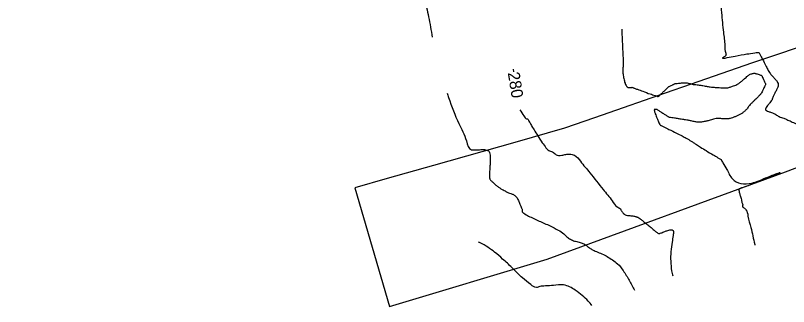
# Model space of a CAD drawing. Extents: x -478232 to -472707, y -1118753 to -1113967.
# Drawn here: x -476364.6 to -476102.7, y -1115350.3 to -1115251.7 of the extents above; entities that cross this region are included whole.
import ezdxf

# ---------------------------------------------------------------- set-up
doc = ezdxf.new("R2010")
doc.units = 0
for name, color, linetype in [('ObPÚ', 7, 'Continuous'), ('Vrstevnice_hlavni', 7, 'Continuous'), ('Vrstevnice_popis', 7, 'Continuous'), ('Vrstevnice_vedlejsi', 7, 'Continuous')]:
    doc.layers.add(name, color=color, linetype=linetype)

msp = doc.modelspace()

# ---------------------------------------------------------------- linework, layer by layer
at = {"layer": 'ObPÚ'}
msp.add_lwpolyline([(-476068.7, -1115252.31), (-476114.88, -1115267.73), (-476138.618, -1115276.003), (-476141.91, -1115277.15), (-476168.45, -1115286.39), (-476178.6, -1115289.93), (-476195.38, -1115294.7), (-476223.04, -1115302.55), (-476238.65, -1115306.98), (-476249.64, -1115310.1), (-476237.84, -1115350.34), (-476184.5, -1115334.29), (-476103.79, -1115304.74), (-476065.34, -1115290.09)], dxfattribs=at)
at = {"layer": 'Vrstevnice_hlavni'}
msp.add_line((-476196.015, -1115269.846), (-476195.861, -1115270.85), dxfattribs=at)
msp.add_spline([(-476193.757, -1115283.639), (-476192.399, -1115285.697), (-476191.876, -1115286.389), (-476191.509, -1115286.744), (-476191.298, -1115286.761), (-476191.153, -1115286.774), (-476191.075, -1115286.783), (-476191.063, -1115286.789), (-476190.853, -1115287.151), (-476190.446, -1115287.871), (-476189.842, -1115288.948), (-476188.923, -1115290.467), (-476187.688, -1115292.429), (-476186.137, -1115294.833), (-476184.891, -1115296.504), (-476183.948, -1115297.443), (-476183.309, -1115297.648), (-476182.68, -1115297.954), (-476182.06, -1115298.362), (-476181.45, -1115298.872), (-476180.595, -1115299.114), (-476179.497, -1115299.088), (-476178.155, -1115298.795), (-476176.997, -1115298.69), (-476176.025, -1115298.773), (-476175.238, -1115299.045), (-476173.224, -1115301.122), (-476169.984, -1115305.003), (-476165.518, -1115310.689), (-476162.449, -1115314.535), (-476160.779, -1115316.54), (-476160.507, -1115316.704), (-476160.264, -1115316.845), (-476160.048, -1115316.962), (-476159.86, -1115317.056), (-476159.707, -1115317.19), (-476159.59, -1115317.365), (-476159.508, -1115317.58), (-476159.311, -1115317.896), (-476158.998, -1115318.315), (-476158.57, -1115318.834), (-476158.007, -1115319.207), (-476157.308, -1115319.433), (-476156.473, -1115319.513), (-476155.76, -1115319.601), (-476155.169, -1115319.698), (-476154.699, -1115319.804), (-476154.303, -1115319.906), (-476153.978, -1115320.004), (-476153.727, -1115320.098), (-476153.145, -1115320.495), (-476152.232, -1115321.193), (-476150.988, -1115322.193), (-476149.831, -1115323.145), (-476148.761, -1115324.046), (-476147.778, -1115324.899), (-476147.017, -1115325.426), (-476146.478, -1115325.629), (-476146.16, -1115325.507), (-476145.635, -1115325.303), (-476144.904, -1115325.017), (-476143.967, -1115324.649), (-476143.233, -1115324.414), (-476142.702, -1115324.312), (-476142.375, -1115324.342), (-476142.123, -1115324.398), (-476141.945, -1115324.481), (-476141.842, -1115324.59), (-476141.767, -1115324.715), (-476141.722, -1115324.858), (-476141.705, -1115325.018), (-476141.842, -1115326.221), (-476142.131, -1115328.466), (-476142.574, -1115331.753), (-476142.636, -1115334.999), (-476142.32, -1115338.203), (-476141.962, -1115339.984)], degree=3, dxfattribs=at)
at = {"layer": 'Vrstevnice_vedlejsi'}
for points in [[(-476527.08, -1115263.803), (-476526.887, -1115263.69), (-476526.162, -1115262.721), (-476524.907, -1115260.894), (-476523.121, -1115258.209), (-476521.764, -1115256.313), (-476520.836, -1115255.206), (-476520.337, -1115254.886), (-476519.366, -1115254.043), (-476517.924, -1115252.676), (-476516.009, -1115250.786), (-476514.302, -1115249.024), (-476512.803, -1115247.392), (-476511.511, -1115245.89), (-476509.929, -1115244.508), (-476508.058, -1115243.246), (-476505.898, -1115242.105), (-476504.014, -1115241.274), (-476502.406, -1115240.753), (-476501.074, -1115240.543), (-476500.026, -1115240.386), (-476499.263, -1115240.283), (-476498.784, -1115240.233), (-476497.172, -1115239.574), (-476494.427, -1115238.305), (-476490.549, -1115236.427), (-476487.653, -1115234.652), (-476485.739, -1115232.982), (-476484.807, -1115231.416), (-476483.874, -1115229.496), (-476482.938, -1115227.221), (-476482, -1115224.593), (-476480.343, -1115222.339), (-476477.964, -1115220.46), (-476474.866, -1115218.956), (-476472.042, -1115216.696), (-476469.492, -1115213.68), (-476467.217, -1115209.908), (-476464.704, -1115205.831), (-476461.955, -1115201.448), (-476458.968, -1115196.76), (-476456.464, -1115193.232), (-476454.442, -1115190.863), (-476452.903, -1115189.654), (-476451.796, -1115188.78), (-476451.122, -1115188.24), (-476450.88, -1115188.036), (-476449.741, -1115187.407), (-476447.705, -1115186.353), (-476444.771, -1115184.875), (-476442.444, -1115183.754), (-476440.723, -1115182.99), (-476439.608, -1115182.582), (-476438.521, -1115182.379), (-476437.462, -1115182.381), (-476436.431, -1115182.589), (-476434.671, -1115182.945), (-476432.182, -1115183.449), (-476428.964, -1115184.102), (-476425.887, -1115183.927), (-476422.953, -1115182.925), (-476420.161, -1115181.095), (-476418.073, -1115179.463), (-476416.69, -1115178.026), (-476416.012, -1115176.786), (-476414.938, -1115175.626), (-476413.47, -1115174.546), (-476411.607, -1115173.546), (-476409.534, -1115172.603), (-476407.252, -1115171.715), (-476404.761, -1115170.883), (-476401.574, -1115169.794), (-476397.69, -1115168.447), (-476393.11, -1115166.843), (-476388.096, -1115165.135), (-476382.647, -1115163.324), (-476376.764, -1115161.408), (-476372.621, -1115160.054), (-476370.219, -1115159.261), (-476369.557, -1115159.028), (-476369.039, -1115158.854), (-476368.663, -1115158.738), (-476368.431, -1115158.68), (-476367.559, -1115158.618), (-476366.047, -1115158.551), (-476363.896, -1115158.479), (-476362.463, -1115158.431), (-476361.747, -1115158.407), (-476361.748, -1115158.407), (-476361.852, -1115158.365), (-476362.059, -1115158.28), (-476362.368, -1115158.152), (-476365.304, -1115157.405), (-476370.868, -1115156.037), (-476379.058, -1115154.05), (-476384.846, -1115152.681), (-476388.232, -1115151.932)], [(-476075.436, -1115157.873), (-476077.562, -1115158.907), (-476079.639, -1115159.964), (-476081.666, -1115161.045), (-476083.644, -1115162.149), (-476085.921, -1115163.289), (-476088.498, -1115164.465), (-476091.373, -1115165.676), (-476093.656, -1115166.843), (-476095.346, -1115167.967), (-476096.444, -1115169.047), (-476097.921, -1115170.165), (-476099.777, -1115171.319), (-476102.012, -1115172.511), (-476105.743, -1115173.677), (-476110.97, -1115174.816), (-476117.692, -1115175.928), (-476122.561, -1115177.005), (-476125.576, -1115178.045), (-476126.738, -1115179.05), (-476129.738, -1115180.989), (-476134.578, -1115183.864), (-476141.257, -1115187.673), (-476147.035, -1115190.356), (-476151.912, -1115191.911), (-476155.888, -1115192.338), (-476158.789, -1115192.754), (-476160.614, -1115193.159), (-476161.364, -1115193.552), (-476162.517, -1115193.939), (-476164.073, -1115194.319), (-476166.032, -1115194.693), (-476167.609, -1115195.158), (-476168.804, -1115195.715), (-476169.616, -1115196.364), (-476170.816, -1115197.116), (-476172.405, -1115197.973), (-476174.383, -1115198.934), (-476179.537, -1115202.555), (-476187.868, -1115208.836), (-476199.377, -1115217.776), (-476207.75, -1115223.932), (-476212.989, -1115227.302), (-476215.093, -1115227.888), (-476217.31, -1115229.046), (-476219.639, -1115230.776), (-476222.081, -1115233.079), (-476224.102, -1115235.091), (-476225.704, -1115236.812), (-476226.884, -1115238.243), (-476227.475, -1115239.561), (-476227.475, -1115240.767), (-476226.885, -1115241.861), (-476225.939, -1115245.662), (-476224.639, -1115252.17), (-476223.41, -1115259.087)], [(-476327.473, -1115168.696), (-476329.504, -1115168.15), (-476331.355, -1115167.757), (-476333.026, -1115167.517), (-476334.516, -1115167.429), (-476335.694, -1115167.418), (-476336.557, -1115167.482), (-476337.107, -1115167.623), (-476338.859, -1115167.867), (-476341.812, -1115168.215), (-476345.968, -1115168.668), (-476348.868, -1115168.973), (-476350.514, -1115169.133), (-476350.905, -1115169.146), (-476351.565, -1115169.254), (-476352.495, -1115169.457), (-476353.694, -1115169.755), (-476355.366, -1115170.663), (-476357.511, -1115172.179), (-476360.129, -1115174.306), (-476363.1, -1115176.798), (-476366.424, -1115179.657), (-476370.101, -1115182.883), (-476375.4, -1115186.443), (-476382.321, -1115190.337), (-476390.863, -1115194.566), (-476396.652, -1115197.445), (-476399.688, -1115198.974), (-476399.971, -1115199.154), (-476400.201, -1115199.316), (-476400.377, -1115199.461), (-476400.5, -1115199.588), (-476400.639, -1115199.703), (-476400.797, -1115199.808), (-476400.971, -1115199.902), (-476403.048, -1115202.383), (-476407.029, -1115207.252), (-476412.913, -1115214.508), (-476418.066, -1115221.099), (-476422.487, -1115227.024), (-476426.176, -1115232.285), (-476429.359, -1115236.354), (-476432.037, -1115239.231), (-476434.209, -1115240.916), (-476436.447, -1115242.554), (-476438.753, -1115244.145), (-476441.124, -1115245.69), (-476442.942, -1115247.528), (-476444.207, -1115249.66), (-476444.917, -1115252.086), (-476445.62, -1115255.263), (-476446.315, -1115259.192), (-476447.003, -1115263.872), (-476447.667, -1115266.918), (-476448.308, -1115268.33), (-476448.925, -1115268.107), (-476449.337, -1115267.958), (-476449.542, -1115267.883), (-476449.542, -1115267.884), (-476449.447, -1115268.421), (-476449.255, -1115269.495), (-476448.968, -1115271.106), (-476448.944, -1115271.994)], [(-476290.943, -1115168.232), (-476292.036, -1115168.129), (-476293.289, -1115168.17), (-476294.704, -1115168.355), (-476296.28, -1115168.684), (-476298.044, -1115169.506), (-476299.998, -1115170.82), (-476302.142, -1115172.626), (-476303.749, -1115173.838), (-476304.822, -1115174.454), (-476305.36, -1115174.476), (-476306.141, -1115174.653), (-476307.165, -1115174.987), (-476308.432, -1115175.476), (-476310.431, -1115176.469), (-476313.163, -1115177.965), (-476316.627, -1115179.965), (-476319.342, -1115180.948), (-476321.309, -1115180.916), (-476322.528, -1115179.868), (-476324.355, -1115178.896), (-476326.789, -1115178.002), (-476329.831, -1115177.184), (-476332.146, -1115176.734), (-476333.735, -1115176.651), (-476334.597, -1115176.934), (-476335.575, -1115177.335), (-476336.67, -1115177.853), (-476337.881, -1115178.489), (-476340.138, -1115179.828), (-476343.441, -1115181.87), (-476347.791, -1115184.616), (-476351.193, -1115186.546), (-476353.648, -1115187.661), (-476355.156, -1115187.959), (-476356.569, -1115188.49), (-476357.888, -1115189.253), (-476359.112, -1115190.247), (-476360.257, -1115191.198), (-476361.323, -1115192.106), (-476362.309, -1115192.972), (-476363.814, -1115193.968), (-476365.837, -1115195.095), (-476368.378, -1115196.353), (-476371.783, -1115197.918), (-476376.05, -1115199.79), (-476381.181, -1115201.968), (-476385.269, -1115204.296), (-476388.314, -1115206.773), (-476390.316, -1115209.399), (-476391.767, -1115211.232), (-476392.667, -1115212.272), (-476393.014, -1115212.519), (-476394.789, -1115214.333), (-476397.991, -1115217.713), (-476402.619, -1115222.659), (-476406.002, -1115226.323), (-476408.139, -1115228.705), (-476409.031, -1115229.805), (-476409.796, -1115230.781), (-476410.434, -1115231.632), (-476410.944, -1115232.36), (-476411.453, -1115232.976), (-476411.961, -1115233.481), (-476412.467, -1115233.874), (-476413.193, -1115235.547), (-476414.139, -1115238.502), (-476415.303, -1115242.737), (-476416.343, -1115247.381), (-476417.259, -1115252.434), (-476418.049, -1115257.897), (-476418.052, -1115258.256)], [(-476125.929, -1115243.884), (-476125.807, -1115246.158), (-476125.427, -1115250.782), (-476124.774, -1115257.383), (-476124.301, -1115261.931), (-476124.008, -1115264.426), (-476123.894, -1115264.868), (-476123.981, -1115265.246), (-476124.269, -1115265.56), (-476124.757, -1115265.811), (-476125.029, -1115265.996), (-476125.083, -1115266.115), (-476124.92, -1115266.169), (-476123.491, -1115265.956), (-476120.797, -1115265.476), (-476116.836, -1115264.728), (-476114.123, -1115264.363), (-476112.657, -1115264.382), (-476112.438, -1115264.783), (-476111.966, -1115265.692), (-476111.241, -1115267.111), (-476110.263, -1115269.038), (-476109.58, -1115270.343), (-476109.193, -1115271.027), (-476109.102, -1115271.089), (-476109.038, -1115271.136), (-476109.003, -1115271.169), (-476108.995, -1115271.186), (-476108.962, -1115271.248), (-476108.904, -1115271.357), (-476108.821, -1115271.512), (-476108.502, -1115271.894), (-476107.946, -1115272.505), (-476107.155, -1115273.343), (-476106.601, -1115274.081), (-476106.285, -1115274.719), (-476106.206, -1115275.258), (-476106.359, -1115275.986), (-476106.744, -1115276.905)], [(-476159.242, -1115256.374), (-476159.054, -1115259.908), (-476158.82, -1115265.295), (-476158.75, -1115268.706), (-476158.845, -1115270.139), (-476158.769, -1115271.604), (-476158.523, -1115273.101), (-476158.106, -1115274.629), (-476157.613, -1115275.635), (-476157.044, -1115276.119), (-476156.398, -1115276.081), (-476155.961, -1115276.055), (-476155.733, -1115276.04), (-476155.713, -1115276.036), (-476155.581, -1115276.081), (-476155.338, -1115276.173), (-476154.983, -1115276.314), (-476153.911, -1115276.714), (-476152.122, -1115277.373), (-476149.617, -1115278.29), (-476147.877, -1115278.87), (-476146.903, -1115279.111), (-476146.694, -1115279.015), (-476146.533, -1115278.92), (-476146.42, -1115278.827), (-476146.354, -1115278.736), (-476146.034, -1115278.42), (-476145.458, -1115277.878), (-476144.627, -1115277.111), (-476144.009, -1115276.53), (-476143.606, -1115276.135), (-476143.416, -1115275.928), (-476143.115, -1115275.721), (-476142.7, -1115275.515), (-476142.174, -1115275.31), (-476141.777, -1115275.132), (-476141.512, -1115274.98), (-476141.376, -1115274.855), (-476140.853, -1115274.744), (-476139.943, -1115274.647), (-476138.645, -1115274.565), (-476137.773, -1115274.512), (-476137.326, -1115274.488), (-476137.304, -1115274.493), (-476137.022, -1115274.564), (-476136.479, -1115274.699), (-476135.676, -1115274.9), (-476135.01, -1115275.037), (-476134.48, -1115275.109), (-476134.087, -1115275.117), (-476133.301, -1115275.213), (-476132.123, -1115275.399), (-476130.553, -1115275.673), (-476129.267, -1115275.873), (-476128.264, -1115275.998), (-476127.545, -1115276.049), (-476126.691, -1115276.105), (-476125.702, -1115276.169), (-476124.578, -1115276.238), (-476123.673, -1115276.222), (-476122.988, -1115276.122), (-476122.522, -1115275.938), (-476121.968, -1115275.735), (-476121.325, -1115275.516), (-476120.594, -1115275.279), (-476119.818, -1115274.872), (-476118.996, -1115274.295), (-476118.13, -1115273.548), (-476117.407, -1115272.922), (-476116.827, -1115272.417), (-476116.391, -1115272.033), (-476115.924, -1115271.733), (-476115.425, -1115271.516), (-476114.896, -1115271.383), (-476114.504, -1115271.301), (-476114.247, -1115271.269), (-476114.127, -1115271.287), (-476113.822, -1115271.374), (-476113.331, -1115271.529), (-476112.656, -1115271.752), (-476112.177, -1115271.921), (-476111.894, -1115272.035), (-476111.807, -1115272.094), (-476111.623, -1115272.416), (-476111.341, -1115273)], [(-476111.341, -1115273), (-476110.962, -1115273.848), (-476110.694, -1115274.441), (-476110.537, -1115274.78), (-476110.491, -1115274.865), (-476110.47, -1115274.959), (-476110.475, -1115275.062), (-476110.506, -1115275.174), (-476110.69, -1115275.573), (-476111.03, -1115276.26), (-476111.524, -1115277.233), (-476111.877, -1115277.912), (-476112.088, -1115278.296), (-476112.158, -1115278.386), (-476112.514, -1115278.752), (-476113.156, -1115279.397), (-476114.085, -1115280.319), (-476114.761, -1115280.979), (-476115.186, -1115281.379), (-476115.36, -1115281.517), (-476115.713, -1115281.919), (-476116.247, -1115282.585), (-476116.962, -1115283.514), (-476117.741, -1115284.291), (-476118.584, -1115284.915), (-476119.493, -1115285.387), (-476120.392, -1115285.812), (-476121.284, -1115286.191), (-476122.167, -1115286.523), (-476123.251, -1115286.707), (-476124.536, -1115286.741), (-476126.022, -1115286.628), (-476127.231, -1115286.643), (-476128.162, -1115286.786), (-476128.816, -1115287.059), (-476129.654, -1115287.316), (-476130.678, -1115287.555), (-476131.887, -1115287.779), (-476133.124, -1115287.833), (-476134.388, -1115287.719), (-476135.68, -1115287.435), (-476136.751, -1115287.215), (-476137.602, -1115287.058), (-476138.232, -1115286.963), (-476139.134, -1115286.827), (-476140.308, -1115286.649), (-476141.754, -1115286.429), (-476142.752, -1115286.26), (-476143.303, -1115286.142), (-476143.406, -1115286.075), (-476143.876, -1115285.775), (-476144.711, -1115285.24), (-476145.912, -1115284.47), (-476146.719, -1115283.95), (-476147.131, -1115283.678), (-476147.149, -1115283.654), (-476147.194, -1115283.626), (-476147.267, -1115283.594), (-476147.366, -1115283.557), (-476147.542, -1115283.533), (-476147.795, -1115283.522), (-476148.124, -1115283.524), (-476148.141, -1115284.035), (-476147.848, -1115285.056), (-476147.243, -1115286.586), (-476146.785, -1115287.691), (-476146.474, -1115288.372), (-476146.31, -1115288.628), (-476146.156, -1115288.817), (-476146.012, -1115288.938), (-476145.878, -1115288.992), (-476144.948, -1115289.442), (-476143.224, -1115290.289), (-476140.705, -1115291.532), (-476138.75, -1115292.524), (-476137.361, -1115293.265), (-476136.537, -1115293.756), (-476135.685, -1115294.285), (-476134.806, -1115294.853), (-476133.899, -1115295.46), (-476132.503, -1115296.342), (-476130.618, -1115297.498), (-476128.243, -1115298.929), (-476126.641, -1115299.885), (-476125.811, -1115300.366), (-476125.755, -1115300.372), (-476125.7, -1115300.405), (-476125.646, -1115300.464), (-476125.594, -1115300.551), (-476124.922, -1115301.679), (-476123.631, -1115303.848), (-476121.721, -1115307.059), (-476118.902, -1115308.612), (-476115.176, -1115308.508), (-476110.541, -1115306.747), (-476107.432, -1115305.567), (-476105.848, -1115304.97)], [(-476106.744, -1115276.905), (-476107.361, -1115278.014), (-476107.805, -1115278.877), (-476108.078, -1115279.493), (-476108.177, -1115279.862), (-476108.25, -1115280.122), (-476108.297, -1115280.271), (-476108.317, -1115280.311), (-476108.573, -1115280.647), (-476109.065, -1115281.28), (-476109.793, -1115282.209), (-476110.279, -1115282.913), (-476110.525, -1115283.392), (-476110.528, -1115283.645), (-476110.197, -1115283.923), (-476109.532, -1115284.226), (-476108.532, -1115284.553), (-476107.69, -1115284.894), (-476107.005, -1115285.251), (-476106.478, -1115285.622), (-476105.861, -1115285.956), (-476105.153, -1115286.251), (-476104.354, -1115286.507), (-476103.257, -1115286.96), (-476101.863, -1115287.61), (-476100.172, -1115288.455), (-476098.717, -1115289.598), (-476097.498, -1115291.039), (-476096.516, -1115292.777), (-476095.725, -1115294.323), (-476095.126, -1115295.678), (-476094.718, -1115296.841), (-476094.281, -1115297.767), (-476093.815, -1115298.456), (-476093.319, -1115298.907), (-476093.04, -1115299.473), (-476092.976, -1115300.153), (-476093.128, -1115300.947), (-476092.975, -1115301.971), (-476092.517, -1115303.223), (-476091.755, -1115304.704), (-476090.913, -1115306.661), (-476089.99, -1115309.094), (-476088.988, -1115312.004), (-476088.293, -1115314.278), (-476087.906, -1115315.919), (-476087.826, -1115316.925), (-476087.506, -1115318.414), (-476087.193, -1115319.54)], [(-476218.376, -1115278.038), (-476217.875, -1115279.456), (-476214.425, -1115288.313), (-476211.835, -1115294.229), (-476210.106, -1115297.205), (-476209.237, -1115297.241), (-476208.349, -1115297.236), (-476207.441, -1115297.189), (-476206.512, -1115297.099), (-476205.696, -1115297.136), (-476204.991, -1115297.297), (-476204.399, -1115297.584), (-476203.999, -1115298.149), (-476203.792, -1115298.991), (-476203.779, -1115300.111), (-476203.805, -1115301.478), (-476203.871, -1115303.093), (-476203.978, -1115304.956), (-476204.004, -1115306.275), (-476203.949, -1115307.051), (-476203.815, -1115307.284), (-476203.415, -1115307.714), (-476202.75, -1115308.342), (-476201.819, -1115309.168), (-476200.943, -1115309.859), (-476200.122, -1115310.415), (-476199.355, -1115310.837), (-476198.758, -1115311.169), (-476198.331, -1115311.411), (-476198.073, -1115311.564), (-476197.577, -1115311.782), (-476196.841, -1115312.065), (-476195.867, -1115312.414), (-476195.041, -1115313.077), (-476194.362, -1115314.054), (-476193.831, -1115315.346), (-476193.423, -1115316.323), (-476193.136, -1115316.986), (-476192.972, -1115317.333), (-476192.894, -1115317.625), (-476192.903, -1115317.861)], [(-476105.848, -1115304.97), (-476105.79, -1115304.953), (-476105.742, -1115304.95), (-476105.706, -1115304.96), (-476105.681, -1115304.983), (-476105.665, -1115305.007), (-476105.66, -1115305.032), (-476105.665, -1115305.057), (-476105.684, -1115305.087), (-476105.717, -1115305.122), (-476105.765, -1115305.16), (-476107.334, -1115305.771), (-476110.427, -1115306.953), (-476115.042, -1115308.707), (-476118.091, -1115309.993), (-476119.575, -1115310.812), (-476119.492, -1115311.162), (-476119.302, -1115311.898), (-476119.003, -1115313.019), (-476118.597, -1115314.525), (-476118.349, -1115315.58), (-476118.261, -1115316.183), (-476118.333, -1115316.335), (-476118.325, -1115316.469), (-476118.238, -1115316.585), (-476118.073, -1115316.683), (-476117.836, -1115316.872), (-476117.529, -1115317.152), (-476117.151, -1115317.523), (-476116.463, -1115319.666), (-476115.466, -1115323.582), (-476114.16, -1115329.271), (-476114.085, -1115329.578)], [(-476192.903, -1115317.861), (-476192.999, -1115318.042), (-476192.816, -1115318.327), (-476192.354, -1115318.716), (-476191.613, -1115319.21), (-476189.891, -1115320.089), (-476187.188, -1115321.354), (-476183.505, -1115323.005), (-476180.713, -1115324.453), (-476178.814, -1115325.697), (-476177.806, -1115326.737), (-476176.612, -1115327.549), (-476175.23, -1115328.132), (-476173.662, -1115328.486), (-476172.346, -1115328.961), (-476171.282, -1115329.555), (-476170.47, -1115330.27), (-476169.305, -1115330.996), (-476167.786, -1115331.732), (-476165.913, -1115332.48), (-476164.102, -1115333.412), (-476162.353, -1115334.527), (-476160.666, -1115335.826), (-476158.775, -1115338.132), (-476156.681, -1115341.444), (-476154.893, -1115344.811)], [(-476169.317, -1115349.984), (-476170.582, -1115348.511), (-476174.959, -1115344.81), (-476178.893, -1115343.028), (-476182.384, -1115343.164), (-476185.085, -1115343.353), (-476186.997, -1115343.594), (-476188.119, -1115343.887), (-476190.063, -1115342.911), (-476192.828, -1115340.664), (-476196.414, -1115337.147), (-476199.562, -1115334.239), (-476202.271, -1115331.942), (-476204.542, -1115330.254), (-476207.149, -1115328.799), (-476207.747, -1115328.526)]]:
    msp.add_spline(points, degree=3, dxfattribs=at)

# ---------------------------------------------------------------- texts
at = {"layer": 'Vrstevnice_popis'}
msp.add_text(' 280 ', height=4, rotation=279.08544, dxfattribs=at).set_placement((-476198.078, -1115269.663))

doc.saveas('drawing.dxf')
